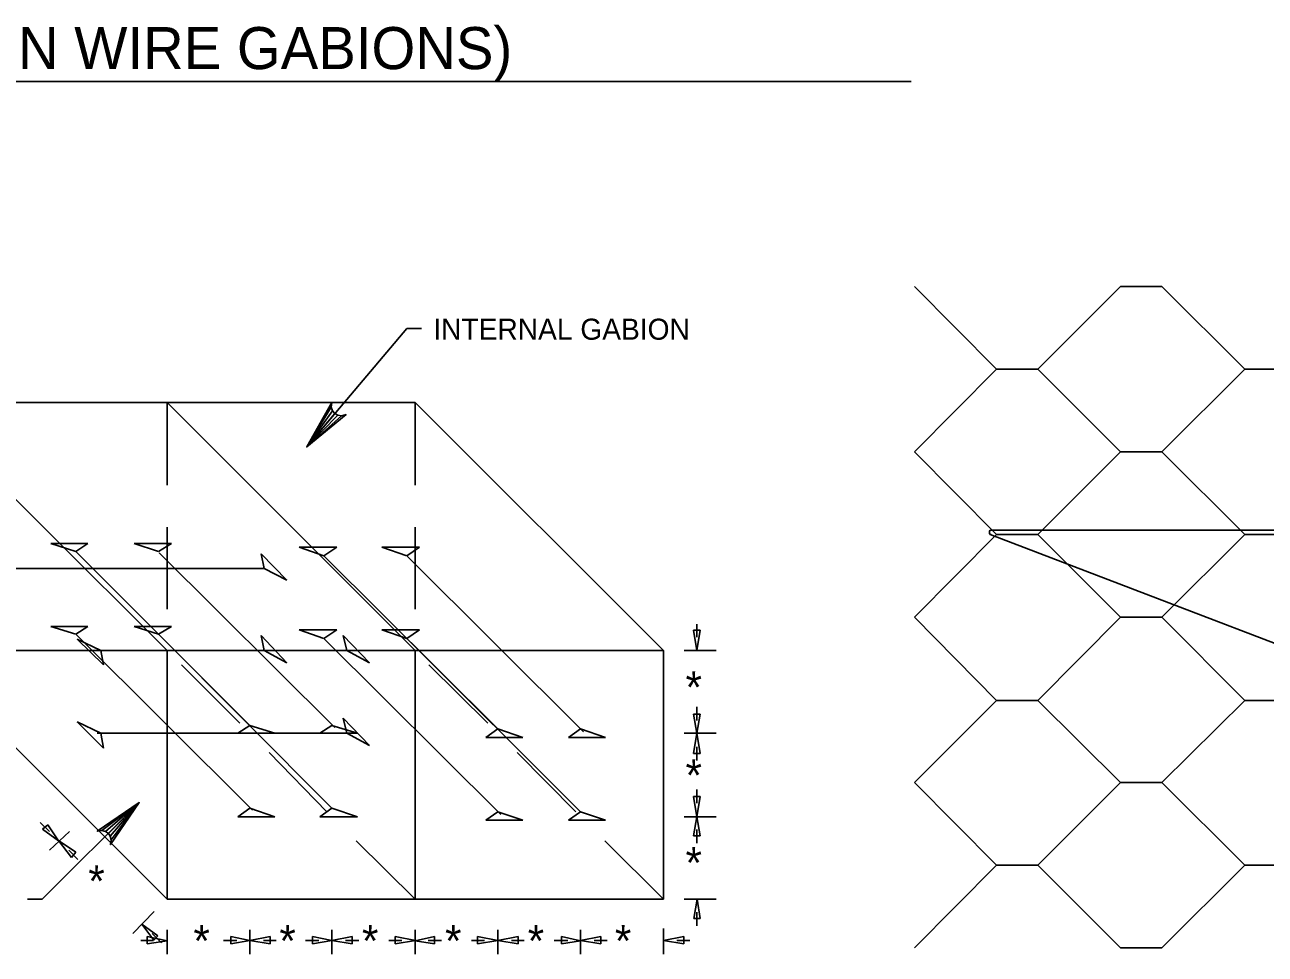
# Model space of a CAD drawing. Extents: x 3 to 3592, y -602 to 1171.
# Drawn here: x 1086.4 to 1263.1, y 286.5 to 419 of the extents above; entities that cross this region are included whole.
import ezdxf

# ---------------------------------------------------------------- set-up
doc = ezdxf.new("R2010")
doc.units = 0
for name, color, linetype in [('2', 7, 'Continuous'), ('3', 7, 'Continuous'), ('H', 7, 'Continuous'), ('P', 7, 'Continuous')]:
    doc.layers.add(name, color=color, linetype=linetype)

msp = doc.modelspace()

# ---------------------------------------------------------------- linework, layer by layer
at = {"layer": '2'}
for points in [[(1126.53, 358.83), (1130.11, 365.14), (1130.04, 364.48), (1126.53, 358.83), (1130.23, 363.95), (1130.54, 363.58), (1126.53, 358.83), (1130.96, 363.34), (1131.5, 363.25), (1126.53, 358.83), (1132.15, 363.42), (1131.5, 363.25), (1130.96, 363.34), (1130.54, 363.58), (1130.23, 363.95), (1130.04, 364.48)], [(1102.66, 308.13), (1098.57, 302.14), (1098.69, 302.8), (1102.66, 308.13), (1098.55, 303.34), (1098.27, 303.73), (1102.66, 308.13), (1097.87, 304.01), (1097.33, 304.15), (1102.66, 308.13), (1096.68, 304.03), (1097.33, 304.15), (1097.87, 304.01), (1098.27, 303.73), (1098.55, 303.34), (1098.69, 302.8)]]:
    msp.add_lwpolyline(points, dxfattribs=at)
at = {"layer": '3'}
msp.add_line((911.87, 410.92), (1212.65, 410.92), dxfattribs=at)
at = {"layer": 'H'}
for p, q in [((1181.67, 332.69), (1182.59, 332.69)), ((1182.13, 329.79), (1181.67, 332.69)), ((1182.59, 332.69), (1182.13, 329.79)), ((1181.67, 320.73), (1182.59, 320.73)), ((1182.13, 317.99), (1181.67, 320.73)), ((1182.59, 320.73), (1182.13, 317.99)), ((1182.13, 318), (1181.67, 315.11)), ((1182.59, 315.11), (1182.13, 318)), ((1181.67, 315.11), (1182.59, 315.11)), ((1181.67, 309), (1182.59, 309)), ((1182.13, 306.1), (1181.67, 309)), ((1182.59, 309), (1182.13, 306.1)), ((1182.13, 306.11), (1181.67, 303.37)), ((1182.59, 303.37), (1182.13, 306.11)), ((1089.66, 304.96), (1088.9, 304.35)), ((1088.9, 304.35), (1091.18, 302.68)), ((1091.18, 302.68), (1089.66, 304.96)), ((1093.01, 300.27), (1091.18, 302.71)), ((1091.18, 302.71), (1093.62, 301.03)), ((1181.67, 303.37), (1182.59, 303.37)), ((1093.62, 301.03), (1093.01, 300.27)), ((1182.15, 294.34), (1181.69, 291.6)), ((1182.6, 291.6), (1182.15, 294.34)), ((1104.73, 288.51), (1103.05, 290.79)), ((1103.05, 290.79), (1105.34, 289.12)), ((1181.69, 291.6), (1182.6, 291.6)), ((1103.78, 289.03), (1103.78, 287.97)), ((1106.67, 288.42), (1103.78, 289.03)), ((1103.78, 287.97), (1106.67, 288.42)), ((1105.34, 289.12), (1104.73, 288.51)), ((1115.71, 289.05), (1115.71, 287.98)), ((1118.45, 288.44), (1115.71, 289.05)), ((1115.71, 287.98), (1118.45, 288.44)), ((1118.42, 288.44), (1121.31, 289.05)), ((1121.31, 287.98), (1118.42, 288.44)), ((1121.31, 289.05), (1121.31, 287.98)), ((1127.36, 289.05), (1127.36, 287.98)), ((1130.1, 288.44), (1127.36, 289.05)), ((1127.36, 287.98), (1130.1, 288.44)), ((1130.11, 288.44), (1133.01, 289.04)), ((1133.01, 287.98), (1130.11, 288.44)), ((1133.01, 289.04), (1133.01, 287.98)), ((1139.12, 289.05), (1139.12, 287.98)), ((1142.02, 288.44), (1139.12, 289.05)), ((1139.12, 287.98), (1142.02, 288.44)), ((1142, 288.42), (1144.74, 289.03)), ((1144.74, 287.97), (1142, 288.42)), ((1144.74, 289.03), (1144.74, 287.97)), ((1150.89, 289.04), (1150.89, 287.98)), ((1153.78, 288.44), (1150.89, 289.04)), ((1150.89, 287.98), (1153.78, 288.44)), ((1153.76, 288.44), (1156.66, 289.05)), ((1156.66, 287.98), (1153.76, 288.44)), ((1156.66, 289.05), (1156.66, 287.98)), ((1162.83, 289.03), (1162.83, 287.97)), ((1165.57, 288.42), (1162.83, 289.03)), ((1162.83, 287.97), (1165.57, 288.42)), ((1165.57, 288.44), (1168.46, 289.05)), ((1168.46, 287.98), (1165.57, 288.44)), ((1168.46, 289.05), (1168.46, 287.98)), ((1177.35, 288.44), (1180.25, 289.04)), ((1180.25, 287.98), (1177.35, 288.44)), ((1180.25, 289.04), (1180.25, 287.98))]:
    msp.add_line(p, q, dxfattribs=at)
at = {"layer": 'P'}
for points in [[(1213.15, 381.7), (1224.83, 369.92)], [(1230.72, 369.92), (1242.51, 381.7)], [(1242.51, 381.7), (1248.4, 381.7)], [(1248.4, 381.7), (1260.19, 369.92)], [(1126.53, 358.83), (1140.78, 375.71)], [(1140.78, 375.71), (1142.91, 375.71)], [(1224.83, 369.92), (1213.15, 358.13)], [(1224.83, 369.92), (1230.72, 369.92)], [(1230.72, 369.92), (1242.51, 358.13)], [(1260.19, 369.92), (1248.4, 358.13)], [(1260.19, 369.92), (1266.18, 369.92)], [(1071.18, 365.14), (1106.64, 329.79)], [(1142, 365.14), (1071.18, 365.14)], [(1106.64, 365.14), (1142, 329.79)], [(1106.64, 365.14), (1106.64, 353.36)], [(1142, 365.14), (1177.35, 329.79)], [(1142, 365.14), (1142, 353.36)], [(1213.15, 358.13), (1224.83, 346.34)], [(1230.72, 346.34), (1242.51, 358.13)], [(1242.51, 358.13), (1248.4, 358.13)], [(1242.51, 358.13), (1248.4, 358.13)], [(1248.4, 358.13), (1260.19, 346.34)], [(1106.64, 347.36), (1106.64, 335.68)], [(1142, 347.36), (1142, 335.68)], [(1224.12, 346.95), (1224.02, 346.95), (1223.82, 346.85), (1223.82, 346.75), (1223.82, 346.75), (1223.82, 346.45), (1223.82, 346.45), (1224.02, 346.34)], [(1224.12, 346.95), (1266.69, 346.95)], [(1093.64, 343.91), (1090.08, 345.03)], [(1093.64, 343.91), (1090.08, 345.03)], [(1090.08, 345.03), (1095.36, 345.03)], [(1090.08, 345.03), (1095.36, 345.03)], [(1095.36, 345.03), (1093.64, 343.91)], [(1095.36, 345.03), (1093.64, 343.91)], [(1101.97, 345.03), (1107.25, 345.03)], [(1105.42, 343.91), (1101.97, 345.03)], [(1105.42, 343.91), (1101.97, 345.03)], [(1101.97, 345.03), (1107.25, 345.03)], [(1107.25, 345.03), (1105.42, 343.91)], [(1107.25, 345.03), (1105.42, 343.91)], [(1224.83, 346.34), (1213.15, 334.56)], [(1293.21, 319.83), (1223.92, 346.34)], [(1224.83, 346.34), (1230.72, 346.34)], [(1230.72, 346.34), (1242.51, 334.56)], [(1260.19, 346.34), (1248.4, 334.56)], [(1260.19, 346.34), (1266.18, 346.34)], [(1118.43, 319.12), (1093.64, 343.91)], [(1105.52, 343.71), (1130.52, 318.81)], [(1123.71, 339.84), (1120.05, 343.6)], [(1123.71, 339.84), (1120.05, 343.6)], [(1120.05, 343.6), (1120.46, 341.47)], [(1120.05, 343.6), (1120.46, 341.47)], [(1125.44, 344.52), (1130.82, 344.52)], [(1125.44, 344.52), (1130.82, 344.52)], [(1128.99, 343.3), (1125.44, 344.52)], [(1128.99, 343.3), (1125.44, 344.52)], [(1130.82, 344.52), (1128.99, 343.3)], [(1130.82, 344.52), (1128.99, 343.3)], [(1153.78, 318.61), (1128.99, 343.3)], [(1137.22, 344.52), (1142.61, 344.52)], [(1140.78, 343.3), (1137.22, 344.52)], [(1140.78, 343.3), (1137.22, 344.52)], [(1137.22, 344.52), (1142.61, 344.52)], [(1142.61, 344.52), (1140.78, 343.3)], [(1142.61, 344.52), (1140.78, 343.3)], [(1140.88, 343.2), (1165.98, 318.2)], [(1120.36, 341.47), (1084.9, 341.47)], [(1120.46, 341.47), (1123.71, 339.84)], [(1120.46, 341.47), (1123.71, 339.84)], [(1213.15, 334.56), (1224.83, 322.67)], [(1230.72, 322.67), (1242.51, 334.56)], [(1242.51, 334.56), (1248.4, 334.56)], [(1242.51, 334.56), (1248.4, 334.56)], [(1248.4, 334.56), (1260.19, 322.67)], [(1090.08, 333.24), (1095.36, 333.24)], [(1093.64, 332.12), (1090.08, 333.24)], [(1093.64, 332.12), (1090.08, 333.24)], [(1090.08, 333.24), (1095.36, 333.24)], [(1095.36, 333.24), (1093.64, 332.12)], [(1095.36, 333.24), (1093.64, 332.12)], [(1101.97, 333.24), (1107.25, 333.24)], [(1105.42, 332.12), (1101.97, 333.24)], [(1105.42, 332.12), (1101.97, 333.24)], [(1101.97, 333.24), (1107.25, 333.24)], [(1107.25, 333.24), (1105.42, 332.12)], [(1107.25, 333.24), (1105.42, 332.12)], [(1125.44, 332.73), (1130.82, 332.73)], [(1125.44, 332.73), (1130.82, 332.73)], [(1128.99, 331.51), (1125.44, 332.73)], [(1128.99, 331.51), (1125.44, 332.73)], [(1130.82, 332.73), (1128.99, 331.51)], [(1130.82, 332.73), (1128.99, 331.51)], [(1137.22, 332.73), (1142.61, 332.73)], [(1140.78, 331.51), (1137.22, 332.73)], [(1140.78, 331.51), (1137.22, 332.73)], [(1137.22, 332.73), (1142.61, 332.73)], [(1142.61, 332.73), (1140.78, 331.51)], [(1142.61, 332.73), (1140.78, 331.51)], [(1182.13, 331.72), (1182.13, 333.55)], [(1093.74, 332.02), (1118.83, 307.03)], [(1097.19, 329.79), (1093.84, 331.41)], [(1097.19, 329.79), (1093.84, 331.41)], [(1097.19, 329.79), (1093.84, 331.41)], [(1097.19, 329.79), (1093.84, 331.41)], [(1093.84, 331.41), (1097.6, 327.75)], [(1093.84, 331.41), (1097.6, 327.75)], [(1093.84, 331.41), (1097.6, 327.75)], [(1093.84, 331.41), (1097.6, 327.75)], [(1130.11, 307.33), (1105.42, 332.12)], [(1123.71, 328.06), (1120.05, 331.92)], [(1123.71, 328.06), (1120.05, 331.92)], [(1120.05, 331.92), (1120.46, 329.79)], [(1120.05, 331.92), (1120.46, 329.79)], [(1129.09, 331.41), (1154.19, 306.42)], [(1135.5, 328.06), (1131.74, 331.92)], [(1135.5, 328.06), (1131.74, 331.92)], [(1131.74, 331.92), (1132.24, 329.79)], [(1131.74, 331.92), (1132.24, 329.79)], [(1165.57, 306.82), (1140.78, 331.51)], [(1071.18, 329.79), (1106.64, 294.33)], [(1120.36, 329.79), (1084.9, 329.79)], [(1088.86, 329.79), (1100.75, 329.79)], [(1095.97, 329.79), (1099.53, 329.79)], [(1132.04, 329.79), (1096.68, 329.79)], [(1097.6, 327.75), (1097.19, 329.79)], [(1097.6, 327.75), (1097.19, 329.79)], [(1097.6, 327.75), (1097.19, 329.79)], [(1097.6, 327.75), (1097.19, 329.79)], [(1106.64, 329.79), (1106.64, 294.33)], [(1106.64, 329.79), (1142, 329.79)], [(1106.64, 329.79), (1142, 329.79)], [(1120.46, 329.79), (1123.71, 328.06)], [(1120.46, 329.79), (1123.71, 328.06)], [(1132.24, 329.79), (1135.5, 328.06)], [(1132.24, 329.79), (1135.5, 328.06)], [(1177.35, 329.79), (1142, 329.79)], [(1142, 329.79), (1142, 294.33)], [(1142, 294.33), (1142, 329.79)], [(1177.35, 294.33), (1177.35, 329.79)], [(1184.87, 329.79), (1180.3, 329.79)], [(1117, 319.42), (1108.67, 327.75)], [(1152.36, 319.42), (1143.93, 327.75)], [(1182.13, 319.83), (1182.13, 321.76)], [(1224.83, 322.67), (1213.15, 310.99)], [(1224.83, 322.67), (1230.72, 322.67)], [(1230.72, 322.67), (1242.51, 310.99)], [(1260.19, 322.67), (1248.4, 310.99)], [(1260.19, 322.67), (1266.18, 322.67)], [(1135.5, 316.27), (1131.74, 320.13)], [(1135.5, 316.27), (1131.74, 320.13)], [(1131.74, 320.13), (1132.24, 318)], [(1131.74, 320.13), (1132.24, 318)], [(1093.84, 319.63), (1097.6, 315.87)], [(1093.84, 319.63), (1097.6, 315.87)], [(1093.84, 319.63), (1097.6, 315.87)], [(1093.84, 319.63), (1097.6, 315.87)], [(1097.19, 318), (1093.84, 319.63)], [(1097.19, 318), (1093.84, 319.63)], [(1097.19, 318), (1093.84, 319.63)], [(1097.19, 318), (1093.84, 319.63)], [(1116.7, 318), (1118.43, 319.12)], [(1116.7, 318), (1118.43, 319.12)], [(1116.7, 318), (1118.43, 319.12)], [(1116.7, 318), (1118.43, 319.12)], [(1118.43, 319.12), (1121.98, 318)], [(1118.43, 319.12), (1121.98, 318)], [(1118.43, 319.12), (1121.98, 318)], [(1118.43, 319.12), (1121.98, 318)], [(1128.38, 318), (1130.11, 319.12)], [(1128.38, 318), (1130.11, 319.12)], [(1130.11, 319.12), (1133.77, 318)], [(1130.11, 319.12), (1133.77, 318)], [(1152.06, 317.39), (1153.78, 318.61)], [(1152.06, 317.39), (1153.78, 318.61)], [(1152.06, 317.39), (1153.78, 318.61)], [(1152.06, 317.39), (1153.78, 318.61)], [(1153.78, 318.61), (1157.34, 317.39)], [(1153.78, 318.61), (1157.34, 317.39)], [(1153.78, 318.61), (1157.34, 317.39)], [(1153.78, 318.61), (1157.34, 317.39)], [(1163.84, 317.39), (1165.57, 318.61)], [(1163.84, 317.39), (1165.57, 318.61)], [(1165.57, 318.61), (1169.13, 317.39)], [(1165.57, 318.61), (1169.13, 317.39)], [(1132.04, 318), (1096.68, 318)], [(1097.6, 315.87), (1097.19, 318)], [(1097.6, 315.87), (1097.19, 318)], [(1097.6, 315.87), (1097.19, 318)], [(1097.6, 315.87), (1097.19, 318)], [(1121.98, 318), (1116.7, 318)], [(1121.98, 318), (1116.7, 318)], [(1121.98, 318), (1116.7, 318)], [(1121.98, 318), (1116.7, 318)], [(1133.77, 318), (1128.38, 318)], [(1133.77, 318), (1128.38, 318)], [(1132.24, 318), (1135.5, 316.27)], [(1132.24, 318), (1135.5, 316.27)], [(1157.34, 317.39), (1152.06, 317.39)], [(1157.34, 317.39), (1152.06, 317.39)], [(1157.34, 317.39), (1152.06, 317.39)], [(1157.34, 317.39), (1152.06, 317.39)], [(1169.13, 317.39), (1163.84, 317.39)], [(1169.13, 317.39), (1163.84, 317.39)], [(1184.87, 318), (1180.3, 318)], [(1184.87, 318), (1180.3, 318)], [(1129.4, 306.82), (1121.17, 315.26)], [(1164.86, 306.82), (1156.53, 315.26)], [(1182.13, 316.07), (1182.13, 314.14)], [(1182.13, 308.04), (1182.13, 309.97)], [(1213.15, 310.99), (1224.83, 299.2)], [(1230.72, 299.2), (1242.51, 310.99)], [(1242.51, 310.99), (1248.4, 310.99)], [(1242.51, 310.99), (1248.4, 310.99)], [(1248.4, 310.99), (1260.19, 299.2)], [(1102.66, 308.13), (1088.86, 294.33)], [(1116.7, 306.11), (1118.43, 307.33)], [(1116.7, 306.11), (1118.43, 307.33)], [(1116.7, 306.11), (1118.43, 307.33)], [(1116.7, 306.11), (1118.43, 307.33)], [(1121.98, 306.11), (1116.7, 306.11)], [(1121.98, 306.11), (1116.7, 306.11)], [(1121.98, 306.11), (1116.7, 306.11)], [(1121.98, 306.11), (1116.7, 306.11)], [(1118.43, 307.33), (1121.98, 306.11)], [(1118.43, 307.33), (1121.98, 306.11)], [(1118.43, 307.33), (1121.98, 306.11)], [(1118.43, 307.33), (1121.98, 306.11)], [(1128.38, 306.11), (1130.11, 307.33)], [(1128.38, 306.11), (1130.11, 307.33)], [(1133.77, 306.11), (1128.38, 306.11)], [(1133.77, 306.11), (1128.38, 306.11)], [(1130.11, 307.33), (1133.77, 306.11)], [(1130.11, 307.33), (1133.77, 306.11)], [(1152.06, 305.61), (1153.78, 306.82)], [(1152.06, 305.61), (1153.78, 306.82)], [(1152.06, 305.61), (1153.78, 306.82)], [(1152.06, 305.61), (1153.78, 306.82)], [(1153.78, 306.82), (1157.34, 305.61)], [(1153.78, 306.82), (1157.34, 305.61)], [(1153.78, 306.82), (1157.34, 305.61)], [(1153.78, 306.82), (1157.34, 305.61)], [(1163.84, 305.61), (1165.57, 306.82)], [(1163.84, 305.61), (1165.57, 306.82)], [(1165.57, 306.82), (1169.13, 305.61)], [(1165.57, 306.82), (1169.13, 305.61)], [(1184.87, 306.11), (1180.3, 306.11)], [(1184.87, 306.11), (1180.3, 306.11)], [(1089.88, 303.98), (1088.56, 305.3)], [(1157.34, 305.61), (1152.06, 305.61)], [(1157.34, 305.61), (1152.06, 305.61)], [(1157.34, 305.61), (1152.06, 305.61)], [(1157.34, 305.61), (1152.06, 305.61)], [(1169.13, 305.61), (1163.84, 305.61)], [(1169.13, 305.61), (1163.84, 305.61)], [(1182.13, 304.28), (1182.13, 302.35)], [(1092.72, 303.98), (1089.88, 301.34)], [(1142, 294.33), (1133.57, 302.66)], [(1177.35, 294.33), (1169.02, 302.66)], [(1092.62, 301.34), (1093.94, 300.02)], [(1224.83, 299.2), (1213.15, 287.42)], [(1224.83, 299.2), (1230.72, 299.2)], [(1230.72, 299.2), (1242.51, 287.42)], [(1260.19, 299.2), (1248.4, 287.42)], [(1260.19, 299.2), (1266.18, 299.2)], [(1088.86, 294.33), (1086.73, 294.33)], [(1106.64, 294.33), (1142, 294.33)], [(1142, 294.33), (1177.35, 294.33)], [(1184.87, 294.33), (1180.3, 294.33)], [(1104.81, 292.6), (1101.76, 289.45)], [(1182.13, 292.5), (1182.13, 290.57)], [(1106.64, 289.96), (1106.64, 286.5)], [(1118.43, 289.96), (1118.43, 286.5)], [(1130.11, 289.96), (1130.11, 286.5)], [(1142, 289.96), (1142, 286.5)], [(1153.78, 289.96), (1153.78, 286.5)], [(1165.57, 289.96), (1165.57, 286.5)], [(1177.35, 290.16), (1177.35, 286.5)], [(1104.71, 288.44), (1102.88, 288.44)], [(1104.51, 289.45), (1105.83, 288.13)], [(1116.6, 288.44), (1114.67, 288.44)], [(1118.43, 288.84), (1118.43, 286.5)], [(1120.36, 288.44), (1122.19, 288.44)], [(1128.28, 288.44), (1126.35, 288.44)], [(1130.11, 288.84), (1130.11, 286.5)], [(1132.04, 288.44), (1133.97, 288.44)], [(1140.07, 288.44), (1138.24, 288.44)], [(1142, 288.84), (1142, 286.5)], [(1143.83, 288.44), (1145.76, 288.44)], [(1151.85, 288.44), (1150.02, 288.44)], [(1153.78, 288.84), (1153.78, 286.5)], [(1155.71, 288.44), (1157.54, 288.44)], [(1163.74, 288.44), (1161.81, 288.44)], [(1165.57, 288.84), (1165.57, 286.5)], [(1167.5, 288.44), (1169.33, 288.44)], [(1179.29, 288.44), (1181.11, 288.44)], [(1242.51, 287.42), (1248.4, 287.42)]]:
    msp.add_lwpolyline(points, dxfattribs=at)

# ---------------------------------------------------------------- texts
at = {"layer": '3'}
for s, height, p in [('CROSS TIE DETAIL (PREFABRICATED WOVEN WIRE GABIONS)', 6, (912.86, 412.67)), ('INTERNAL GABION', 3, (1144.57, 374.1)), ('*', 4.5, (1180.51, 322.32)), ('*', 4.5, (1180.51, 309.77)), ('*', 4.5, (1180.51, 297.29)), ('*', 4.5, (1095.41, 294.68)), ('*', 4.5, (1110.39, 286.16)), ('*', 4.5, (1122.64, 286.16)), ('*', 4.5, (1134.41, 286.16)), ('*', 4.5, (1146.25, 286.16)), ('*', 4.5, (1158.03, 286.16)), ('*', 4.5, (1170.45, 286.16))]:
    msp.add_text(s, height=height, dxfattribs=at).set_placement(p)

doc.saveas('drawing.dxf')
